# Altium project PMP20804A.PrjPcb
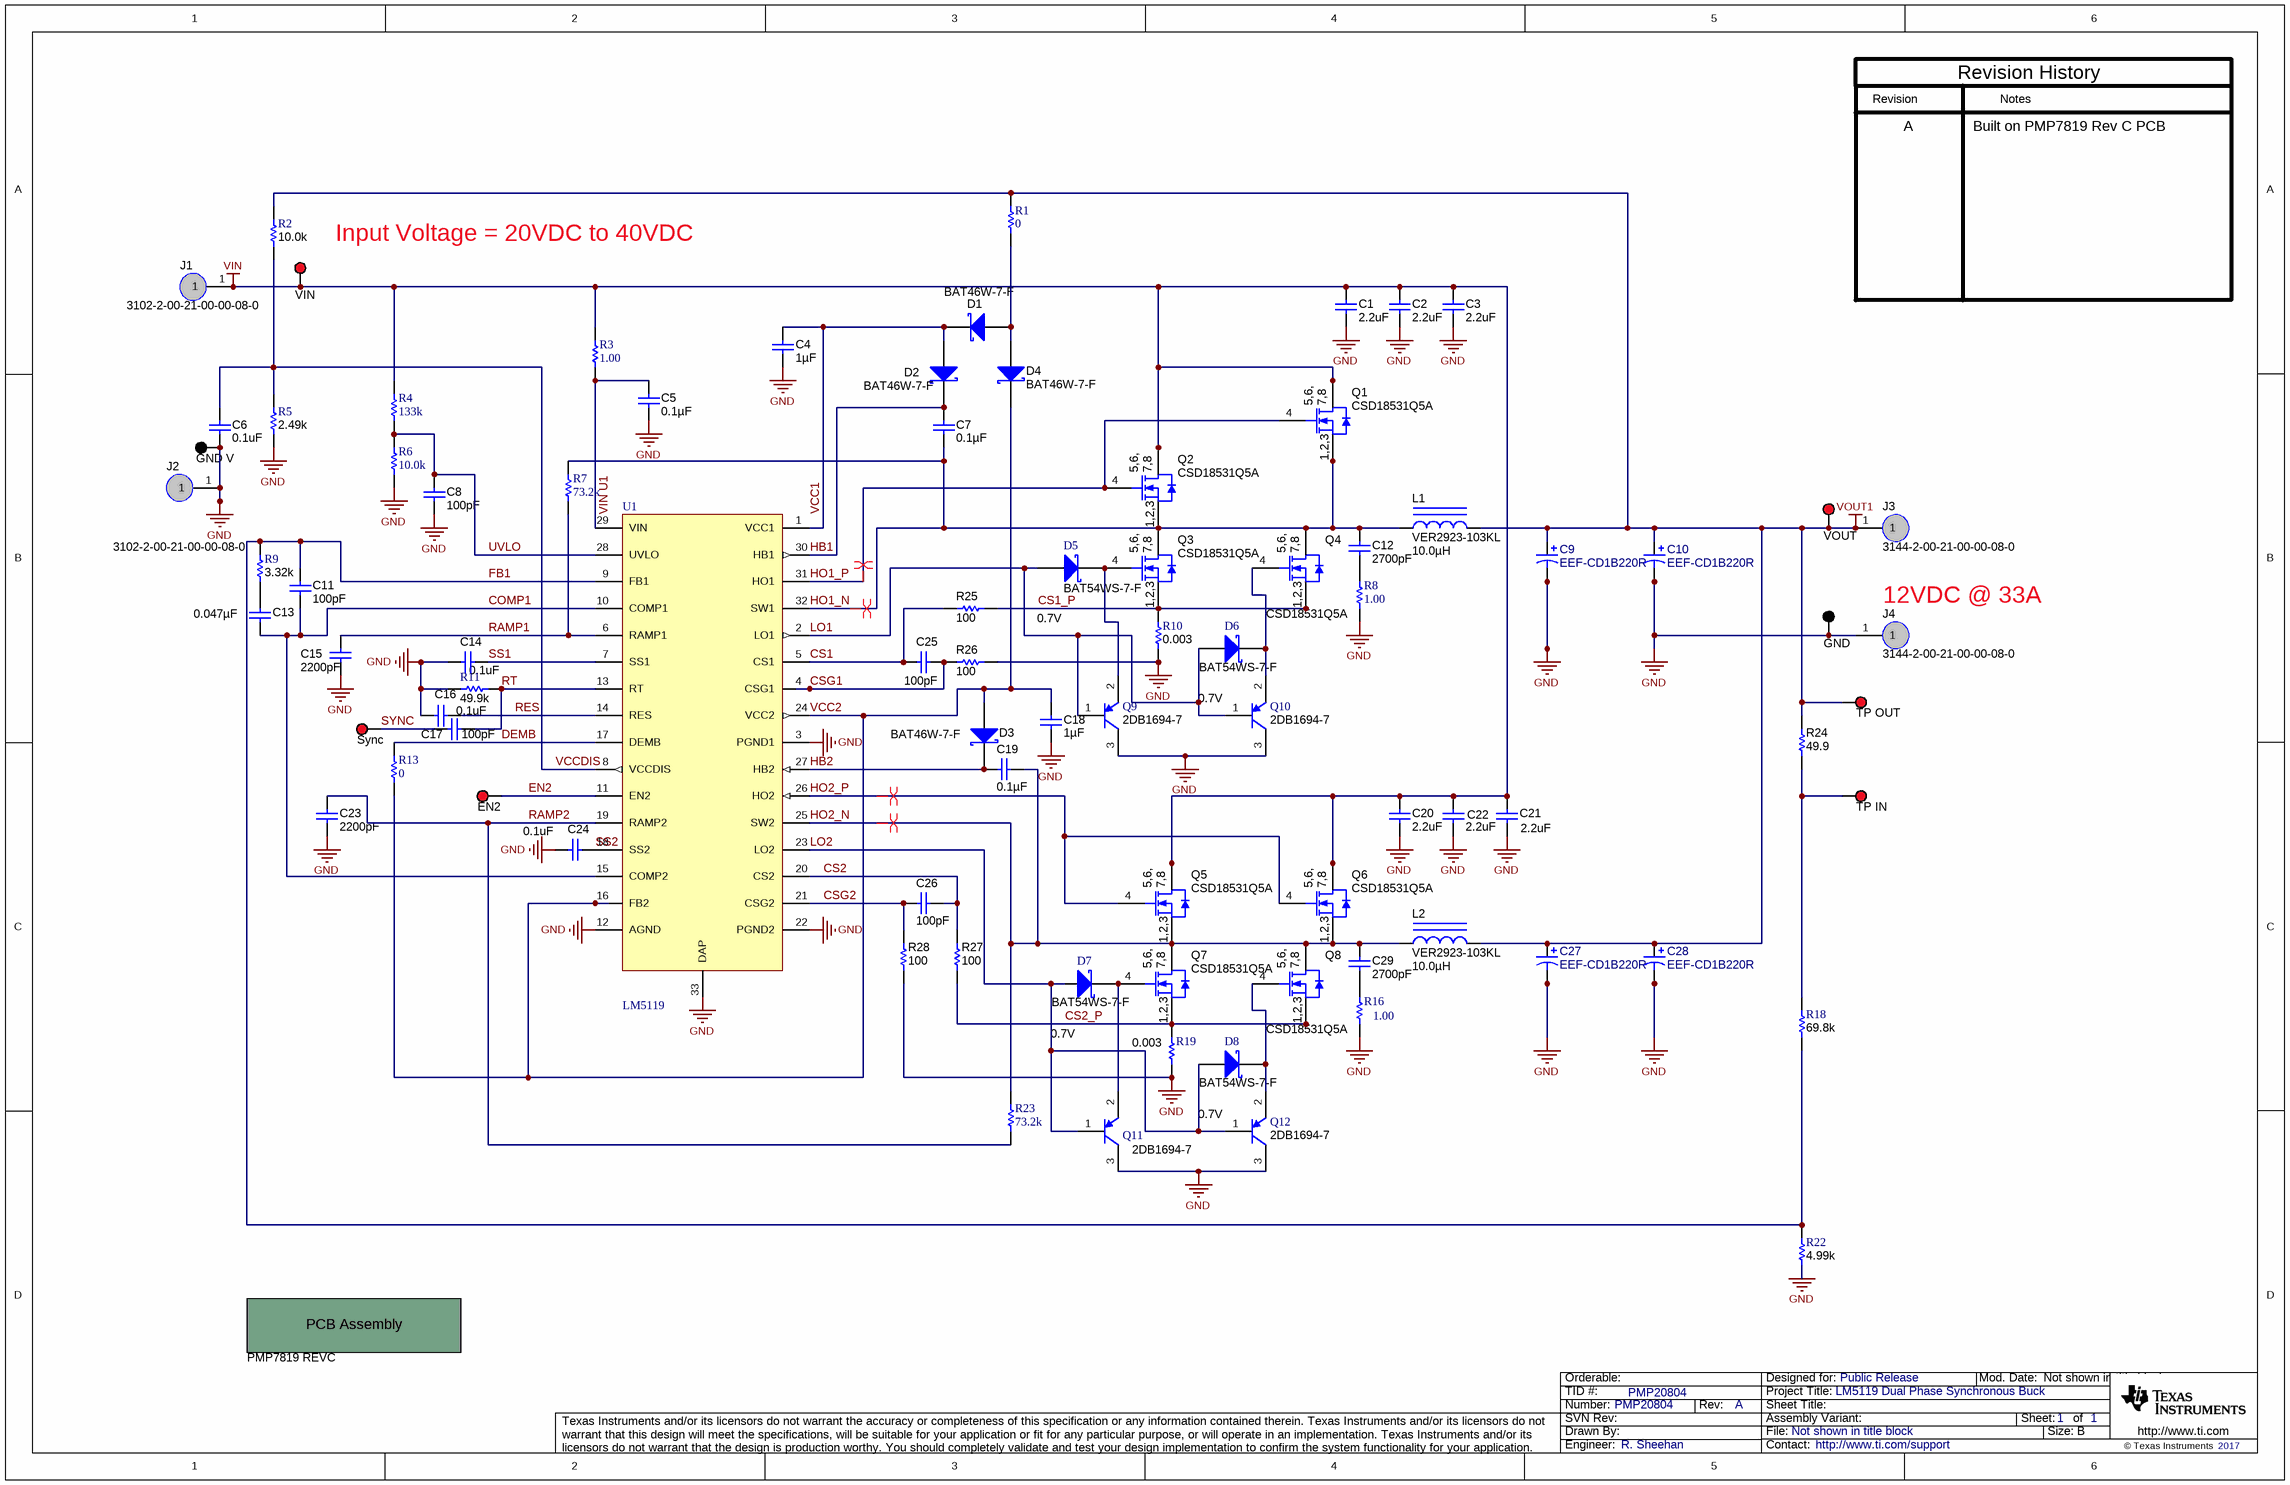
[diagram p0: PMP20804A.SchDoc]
CopyrightYear: 2017; PCB_Rev: C; PRJ_Customer: Public Release; PRJ_Engineer: R. Sheehan; PRJ_Number: PMP20804; PRJ_Title: LM5119 Dual Phase Synchronous Buck; SCH_Rev: A; TechSupport: http://www.ti.com/support; TID: PMP20804
1 sheet, 87 parts. Net scope: global (net labels, ports and power ports of the same name join across sheets).
Board file: PMP7819 REVC.PcbDoc

## Sheet PMP20804A.SchDoc
size 431 x 279 mm; Date: Not shown in title block; ApprovedBy: Not shown in title block; CheckedBy: Not shown in title block; Author: Not shown in title block; CompanyName: Not shown in title block; Engineer: Not shown in title block; Organization: Not shown in title block; Address1: Not shown in title block; Address2: Not shown in title block; Address3: Not shown in title block; Address4: Not shown in title block; DocumentNumber: 1; Revision: Use project parameter SCH_Rev; SheetNumber: 1; SheetTotal: 1; PageSetup: Record=PageOptions¦CenterHorizontal=True¦CenterVertical=True¦PrintScale=1.00¦XCorrection=1.00¦YCorrection=1.00¦PrintKind=0¦BorderSize=5000000¦LeftOffset=0¦BottomOffset=0¦Orientation=2¦PaperLength=1000¦PaperWidth=1000¦Scale=100¦PaperSource=15¦PrintQuality=600¦MediaType=1¦DitherType=10¦PaperKind=Letter¦PrintScaleMode=1

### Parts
!PCBA  PMP7819 REVC  (mechanical)
C1  value 2.2uF  [1210]  (hidden comment: HMK325B7225KN-T)
C2  value 2.2uF  [1210]  (hidden comment: HMK325B7225KN-T)
C3  value 2.2uF  [1210]  (hidden comment: HMK325B7225KN-T)
C4  ValueDisplayed: 1µF  [0603]  (hidden comment: GRM188R71C105KA12D)
C5  ValueDisplayed: 0.1µF  [0805_HV]  (hidden comment: C2012X7R2A104K)
C6  value 0.1uF  [0603]  (hidden comment: C1608X7R1H104K)
C7  ValueDisplayed: 0.1µF  [0603]  (hidden comment: GRM188R72A104KA35D)
C8  value 100pF  [0603]  (hidden comment: 06035A101JAT2A)
C9  EEF-CD1B220R  [CD SP-CAP]
C10  EEF-CD1B220R  [CD SP-CAP]
C11  value 100pF  [0603]  (hidden comment: 06035A101JAT2A)
C12  ValueDisplayed: 2700pF  [0603]  (hidden comment: 06031C272JAT2A)
C13  ValueDisplayed: 0.047µF  [0603]  (hidden comment: C1608X7R1H473K)
C14  value 0.1uF  [0603]  (hidden comment: C1608X7R1H104K)
C15  ValueDisplayed: 2200pF  [0603]  (hidden comment: C0603C222K5RACTU)
C16  value 0.1uF  [0603]  (hidden comment: C1608X7R1H104K)
C17  value 100pF  [0603]  (hidden comment: 06035A101JAT2A)
C18  ValueDisplayed: 1µF  [0603]  (hidden comment: GRM188R71C105KA12D)
C19  ValueDisplayed: 0.1µF  [0603]  (hidden comment: GRM188R72A104KA35D)
C20  value 2.2uF  [1210]  (hidden comment: HMK325B7225KN-T)
C21  value 2.2uF  [1210]  (hidden comment: HMK325B7225KN-T)
C22  value 2.2uF  [1210]  (hidden comment: HMK325B7225KN-T)
C23  ValueDisplayed: 2200pF  [0603]  (hidden comment: C0603C222K5RACTU)
C24  value 0.1uF  [0603]  (hidden comment: C1608X7R1H104K)
C25  ValueDisplayed: 100pF  [0603]  (hidden comment: GRM1885C1H101JA01D)
C26  ValueDisplayed: 100pF  [0603]  (hidden comment: GRM1885C1H101JA01D)
C27  EEF-CD1B220R  [CD SP-CAP]
C28  EEF-CD1B220R  [CD SP-CAP]
C29  ValueDisplayed: 2700pF  [0603]  (hidden comment: 06031C272JAT2A)
D1  BAT46W-7-F  [SOD-123]
D2  BAT46W-7-F  [SOD-123]
D3  BAT46W-7-F  [SOD-123]
D4  BAT46W-7-F  [SOD-123]
D5  BAT54WS-7-F  value 0.7V  [sod-323]
D6  BAT54WS-7-F  value 0.7V  [sod-323]
D7  BAT54WS-7-F  value 0.7V  [sod-323]
D8  BAT54WS-7-F  value 0.7V  [sod-323]
EN2  5000  [Keystone5000]  (value not drawn)
GND  5001  [Keystone5001]  (value not drawn)
GND_V  5001  [Keystone5001]  (value not drawn)
J1  3102-2-00-21-00-00-08-0  [3102-2-00-21-00-00-08-0]
J2  3102-2-00-21-00-00-08-0  [3102-2-00-21-00-00-08-0]
J3  3144-2-00-21-00-00-08-0  [3144-2-00-21-00-00-08-0]
J4  3144-2-00-21-00-00-08-0  [3144-2-00-21-00-00-08-0]
L1  VER2923-103KL  ValueDisplayed: 10.0µH  [VER2923]
L2  VER2923-103KL  ValueDisplayed: 10.0µH  [VER2923]
Q1  CSD18531Q5A  [DQJ0008A]
Q2  CSD18531Q5A  [DQJ0008A]
Q3  CSD18531Q5A  [DQJ0008A]
Q4  CSD18531Q5A  [DQJ0008A]
Q5  CSD18531Q5A  [DQJ0008A]
Q6  CSD18531Q5A  [DQJ0008A]
Q7  CSD18531Q5A  [DQJ0008A]
Q8  CSD18531Q5A  [DQJ0008A]
Q9  2DB1694-7  [SOT-323 DIODES INC]
Q10  2DB1694-7  [SOT-323 DIODES INC]
Q11  2DB1694-7  [SOT-323 DIODES INC]
Q12  2DB1694-7  [SOT-323 DIODES INC]
R1  value 0  [0603]  (hidden comment: CRCW06030000Z0EA)
R2  value 10.0k  [0603]  (hidden comment: CRCW060310K0FKEA)
R3  value 1.00  [0805_HV]  (hidden comment: CRCW08051R00FNEA)
R4  value 133k  [0603]  (hidden comment: CRCW0603133KFKEA)
R5  value 2.49k  [0603]  (hidden comment: CRCW06032K49FKEA)
R6  value 10.0k  [0603]  (hidden comment: CRCW060310K0FKEA)
R7  value 73.2k  [0603]  (hidden comment: CRCW060373K2FKEA)
R8  value 1.00  [1206]  (hidden comment: CRCW12061R00FNEA)
R9  value 3.32k  [0603]  (hidden comment: CRCW06033K32FKEA)
R10  value 0.003  [2010M]  (hidden comment: WSL20103L000FEA)
R11  value 49.9k  [0603]  (hidden comment: CRCW060349K9FKEA)
R13  value 0  [0603]  (hidden comment: CRCW06030000Z0EA)
R16  value 1.00  [1206]  (hidden comment: CRCW12061R00FNEA)
R18  value 69.8k  [0603]  (hidden comment: CRCW060369K8FKEA)
R19  value 0.003  [2010M]  (hidden comment: WSL20103L000FEA)
R22  value 4.99k  [0603]  (hidden comment: CRCW06034K99FKEA)
R23  value 73.2k  [0603]  (hidden comment: CRCW060373K2FKEA)
R24  value 49.9  [0603]  (hidden comment: CRCW060349R9FKEA)
R25  value 100  [0603]  (hidden comment: CRCW0603100RFKEA)
R26  value 100  [0603]  (hidden comment: CRCW0603100RFKEA)
R27  value 100  [0603]  (hidden comment: CRCW0603100RFKEA)
R28  value 100  [0603]  (hidden comment: CRCW0603100RFKEA)
Sync  5000  [Keystone5000]  (value not drawn)
TP_IN  5000  [Keystone5000]  (value not drawn)
TP_OUT  5000  [Keystone5000]  (value not drawn)
U1  LM5119  [SQA32A]
VIN  5000  [Keystone5000]  (value not drawn)
VOUT  5000  [Keystone5000]  (value not drawn)

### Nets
GND: C1.2 C2.2 C3.2 C4.2 C5.2 C6.2 C8.2 C9.2(-) C9.3(-) C10.2(-) C10.3(-) C14.2 C15.2 C16.2 C18.2 C20.2 C21.2 C22.2 C23.2 C24.2 C27.2(-) C27.3(-) C28.2(-) C28.3(-) GND.1 GND_V.1 J2.1 J4.1 Q9.3(C) Q10.3(C) Q11.3(C) Q12.3(C) R5.2 R6.1 R8.2 R10.1 R11.1 R16.2 R19.1 R22.1 R26.2 R28.1 U1.3(PGND1) U1.12(AGND) U1.22(PGND2) U1.33(DAP)
VIN: C1.1 C2.1 C3.1 C20.1 C21.1 C22.1 J1.1 Q1.5(D) Q1.6(D) Q1.7(D) Q1.8(D) Q1.9(D) Q2.5(D) Q2.6(D) Q2.7(D) Q2.8(D) Q2.9(D) Q5.5(D) Q5.6(D) Q5.7(D) Q5.8(D) Q5.9(D) Q6.5(D) Q6.6(D) Q6.7(D) Q6.8(D) Q6.9(D) R3.2 R4.2 VIN.1
VOUT1: C9.1(+) C10.1(+) C27.1(+) C28.1(+) J3.1 L1.2 L2.2 R1.1 R2.2 R24.2 TP_OUT.1 VOUT.1
COMP1: C11.2 C13.2 U1.10(COMP1) U1.15(COMP2)
CS1: C25.2 R25.1 U1.5(CS1)
CS1_P: Q3.1(S) Q3.2(S) Q3.3(S) Q4.1(S) Q4.2(S) Q4.3(S) R10.2 R25.2
CS2: C26.1 R27.2 U1.20(CS2)
CS2_P: Q7.1(S) Q7.2(S) Q7.3(S) Q8.1(S) Q8.2(S) Q8.3(S) R19.2 R27.1
CSG1: C25.1 R26.1 U1.4(CSG1)
CSG2: C26.2 R28.2 U1.21(CSG2)
DEMB: R13.2 U1.17(DEMB)
EN2: EN2.1 U1.11(EN2)
FB1: C11.1 R9.2 R18.1 R22.2 U1.9(FB1)
HB1: C7.2 D2.1(K) U1.30(HB1)
HB2: C19.1 D3.1(K) U1.27(HB2)
HO1_N: C7.1 C12.1 L1.1 Q1.1(S) Q1.2(S) Q1.3(S) Q2.1(S) Q2.2(S) Q2.3(S) Q3.5(D) Q3.6(D) Q3.7(D) Q3.8(D) Q3.9(D) Q4.5(D) Q4.6(D) Q4.7(D) Q4.8(D) Q4.9(D) R7.2 U1.32(SW1)
HO1_P: Q1.4(G) Q2.4(G) U1.31(HO1)
HO2_N: C19.2 C29.1 L2.1 Q5.1(S) Q5.2(S) Q5.3(S) Q6.1(S) Q6.2(S) Q6.3(S) Q7.5(D) Q7.6(D) Q7.7(D) Q7.8(D) Q7.9(D) Q8.5(D) Q8.6(D) Q8.7(D) Q8.8(D) Q8.9(D) R23.2 U1.25(SW2)
HO2_P: Q5.4(G) Q6.4(G) U1.26(HO2)
LO1: D5.2(A) D6.2(A) Q9.1(B) Q10.1(B) U1.2(LO1)
LO2: D7.2(A) D8.2(A) Q11.1(B) Q12.1(B) U1.23(LO2)
RAMP1: C15.1 R7.1 U1.6(RAMP1)
RAMP2: C23.1 R23.1 U1.19(RAMP2)
RES: C16.1 U1.14(RES)
RT: C17.2 R11.2 U1.13(RT)
SS1: C14.1 U1.7(SS1)
SS2: C24.1 U1.18(SS2)
SYNC: C17.1 Sync.1
UVLO: C8.1 R4.1 R6.2 U1.28(UVLO)
VCC1: C4.1 D1.1(K) D2.2(A) U1.1(VCC1)
VCC2: C18.1 D3.2(A) D4.1(K) R13.1 U1.16(FB2) U1.24(VCC2)
VCCDIS: C6.1 R2.1 R5.1 U1.8(VCCDIS)
VIN U1: C5.1 R3.1 U1.29(VIN)
NetC12_2: C12.2 R8.1
NetC13_1: C13.1 R9.1
NetC29_2: C29.2 R16.1
NetD1_2: D1.2(A) D4.2(A) R1.2
NetD5_1: D5.1(K) Q3.4(G) Q9.2(E)
NetD6_1: D6.1(K) Q4.4(G) Q10.2(E)
NetD7_1: D7.1(K) Q7.4(G) Q11.2(E)
NetD8_1: D8.1(K) Q8.4(G) Q12.2(E)
NetR18_2: R18.2 R24.1 TP_IN.1

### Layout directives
differential pair: HO1_N, HO1_P, HO2_N, HO2_P

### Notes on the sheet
- Revision
- Notes
- Revision History
- A
- Built on PMP7819 Rev C PCB
- Input Voltage = 20VDC to 40VDC
- (near J4) 12VDC @ 33A

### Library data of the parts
!PCBA = PCBA: SymbolCreator: a0412235; U/M: EA
C1-C3 C20-C22 = HMK325B7225KN-T: CAP, CERM, 2.2uF, 100V, +/-10%, X7R, 1210; Manufacturer: Taiyo Yuden; Polarized: N; TaMax_C: 125; TaMin_C: -55; Tolerance_%: 10; VDC_V: 100; Cap_F: 0.0000022; CompType: Capacitor; U/M: EA; ValueDisplayed: 2.2µF
C4 C18 = GRM188R71C105KA12D: CAP, CERM, 1uF, 16V, +/-10%, X7R, 0603; Manufacturer: MuRata; ESR_Ohm: 0.011; Polarized: N; TaMax_C: 125; TaMin_C: -55; Tolerance_%: 10; VDC_V: 16; Cap_F: 0.000001; CompType: Capacitor; U/M: EA; Value1: 0.011 ohm
C5 = C2012X7R2A104K: CAP, CERM, 0.1uF, 100V, +/-10%, X7R, 0805; Manufacturer: TDK; Cap_Case: 0805; ESR_Ohm: 0.0158; Polarized: N; TaMax_C: 125; TaMin_C: -55; Tolerance_%: 10; VDC_V: 100; Cap_F: 0.0000001; CompType: Capacitor; Value1: 0.0158 ohm; U/M: EA
C6 C14 C16 C24 = C1608X7R1H104K: CAP, CERM, 0.1uF, 50V, +/-10%, X7R, 0603; Manufacturer: TDK; ESR_Ohm: 0.017; Polarized: N; TaMax_C: 125; TaMin_C: -55; Tolerance_%: 10; VDC_V: 50; Cap_F: 0.0000001; CompType: Capacitor; Value1: 0.017 ohm; U/M: EA; ValueDisplayed: 0.1µF
C7 C19 = GRM188R72A104KA35D: CAP, CERM, 0.1uF, 100V, +/-10%, X7R, 0603; Manufacturer: MuRata; Polarized: N; TaMax_C: 125; TaMin_C: -55; Tolerance_%: 10; VDC_V: 100; Cap_F: 0.0000001; CompType: Capacitor; U/M: EA
C8 C11 C17 = 06035A101JAT2A: CAP, CERM, 100pF, 50V, +/-5%, C0G/NP0, 0603; Manufacturer: AVX; ESR_Ohm: 0.119; Polarized: N; TaMax_C: 125; TaMin_C: -55; Tolerance_%: 5; VDC_V: 50; Cap_F: 0.0000000001; CompType: Capacitor; Value1: 0.119 ohm; U/M: EA
C9 C10 C27 C28 = EEF-CD1B220R: CAP ALUM 22UF 12.5V 20% SMD; Manufacturer: Panasonic-ECG; CompType: Used in BOM report; SymbolVersion: 2012 - 04 - 16; SymbolCreator: cdnlsc
C12 C29 = 06031C272JAT2A: CAP, CERM, 2700pF, 100V, +/-5%, X7R, 0603; Manufacturer: AVX; ESR_Ohm: 0.174; Polarized: N; TaMax_C: 125; TaMin_C: -55; Tolerance_%: 5; VDC_V: 100; Cap_F: 0.0000000027; CompType: Capacitor; Value1: 0.174 ohm; U/M: EA
C13 = C1608X7R1H473K: CAP, CERM, 0.047uF, 50V, +/-10%, X7R, 0603; Manufacturer: TDK; ESR_Ohm: 0.0234; Polarized: N; TaMax_C: 125; TaMin_C: -55; Tolerance_%: 10; VDC_V: 50; Cap_F: 0.000000047; CompType: Capacitor; Value1: 0.0234 ohm; U/M: EA
C15 C23 = C0603C222K5RACTU: CAP, CERM, 2200pF, 50V, +/-10%, X7R, 0603; Manufacturer: Kemet; Polarized: N; TaMax_C: 125; TaMin_C: -55; Tolerance_%: 10; VDC_V: 50; Cap_F: 0.0000000022; CompType: Capacitor; U/M: EA
C25 C26 = GRM1885C1H101JA01D: CAP, CERM, 100pF, 50V, +/-5%, C0G/NP0, 0603; Manufacturer: MuRata; Polarized: N; CompType: Capacitor; U/M: EA; Cap_F: 0.0000000001; Tolerance_%: 5; VDC_V: 50; TaMin_C: -55; TaMax_C: 125
D1-D4 = BAT46W-7-F: Diode, Schottky, 100V, 0.15A, SOD-123; Manufacturer: Diodes Inc.; Vf_V: 0.6; Io_A: 0.15; Vr_V: 100; Value: 0.6V; U/M: EA
D5-D8 = BAT54WS-7-F: Diode, Schottky, 30V, 0.2A, SOD-323; Manufacturer: Diodes Inc.; U/M: EA; Vf_V: 0.7; Io_A: 0.2; Vr_V: 30; TJmax_C: 125
EN2 Sync TP_IN TP_OUT VIN VOUT = 5000: Test Point, TH, Miniature, Red; Manufacturer: Keystone; CompType: Test Point Loop; U/M: EA
GND GND_V = 5001: Test Point, TH, Miniature, Black; Manufacturer: Keystone; CompType: Test Point Loop; U/M: EA
J1 J2 = 3102-2-00-21-00-00-08-0: PC PIN .040 DIA 3102-2 SERIES; Manufacturer: Mill -Max; SymbolVersion: 2011 - 12 - 16; SymbolCreator: cdnlsc; U/M: EA
J3 J4 = 3144-2-00-21-00-00-08-0: CIRCUIT PIN PRNTD .188" .084"; Manufacturer: Mill -Max; SymbolVersion: 2011 - 12 - 16; SymbolCreator: cdnlsc; U/M: EA
L1 L2 = VER2923-103KL: Inductor, Shielded E Core, Ferrite, 10.0uH, 34A, .0023 ohm, SMD; Manufacturer: Coilcraft; Ind_H: 3.3E-6; Imax_A: 30; DCR_ohm: 0.0015; Value1: 0.0023 ohm; Value2: 34.0; U/M: EA
Q1-Q8 = CSD18531Q5A: MOSFET, N-CH, 60 V, 100 A, DQJ0008A (VSONP-8); Manufacturer: Texas Instruments; Alternate Manufacturer: None; Value: 60V; ChType: N; VdsMax_V: 60; Value1: 0.0058 ohm; Rdson45_ohm: 0.0058; Value2: 36 nC; QgTyp_nC: 36; Vgs_V: 20; IdsMax_A: 100; U/M: EA; SizeAreaWB_mm2: 55.2; SizeArea_mm2: 29.4; SizeX_mm: 6; SizeY_mm: 4.9; SizeZ_mm: 1.1; AEC Category: Q101
Q9-Q12 = 2DB1694-7: TRANS BIPO PNP 30V 1A SOT-323; Manufacturer: Diodes Inc.; CompType: BJT; U/M: EA; PNP: 1; NPN: 0; Vceo_V: 30; Vcesat1_V: 0.075; Value: 0.075V; IcRated_A: 0.1; Value1: 0.1A; HfeMax: 600
R1 R13 = CRCW06030000Z0EA: RES, 0 ohm, 5%, 0.1W, 0603; Manufacturer: Vishay-Dale; CompType: Resistor; Tolerance_%: 5; VDC_V: 75; Power_W: 0.1; Value_Code: 0000; EIA_Code: E24; U/M: EA
R2 = CRCW060310K0FKEA: RES, 10.0k ohm, 1%, 0.1W, 0603; Manufacturer: Vishay-Dale; CompType: Resistor; Tolerance_%: 1; VDC_V: 75; Power_W: 0.1; Res_ohm: 10000; Value_Code: 10k0; EIA_Code: E96; U/M: EA; TempCo: 100 ppm/C
R3 = CRCW08051R00FNEA: RES, 1.00 ohm, 1%, 0.125W, 0805; Manufacturer: Vishay-Dale; CompType: Resistor; Tolerance_%: 1; VDC_V: 150; Power_W: 0.125; Value_Code: 1R00; EIA_Code: E96; U/M: EA
R4 = CRCW0603133KFKEA: RES, 133k ohm, 1%, 0.1W, 0603; Manufacturer: Vishay-Dale; CompType: Resistor; Tolerance_%: 1; VDC_V: 75; Power_W: 0.1; Res_Ohm: 133000; EIA_Code: E96; U/M: EA
R5 = CRCW06032K49FKEA: RES, 2.49k ohm, 1%, 0.1W, 0603; Manufacturer: Vishay-Dale; CompType: Resistor; Tolerance_%: 1; VDC_V: 75; Power_W: 0.1; Res_ohm: 2490; Value_Code: 2k49; EIA_Code: E96; U/M: EA; TempCo: 100 ppm/C
R6 = CRCW060310K0FKEA: RES, 10.0k ohm, 1%, 0.1W, 0603; Manufacturer: Vishay-Dale; CompType: Resistor; Tolerance_%: 1; VDC_V: 75; Power_W: 0.1; Res_Ohm: 10000; Value_Code: 10k0; EIA_Code: E96; U/M: EA
R7 R23 = CRCW060373K2FKEA: RES, 73.2k ohm, 1%, 0.1W, 0603; Manufacturer: Vishay-Dale; CompType: Resistor; Tolerance_%: 1; VDC_V: 75; Power_W: 0.1; Res_Ohm: 73200; Value_Code: 73k2; EIA_Code: E96; U/M: EA
R8 R16 = CRCW12061R00FNEA: RES, 1.00 ohm, 1%, 0.25W, 1206; Manufacturer: Vishay-Dale; CompType: Resistor; Tolerance_%: 1; VDC_V: 200; Power_W: 0.25; Value_Code: 1R00; EIA_Code: E96; U/M: EA
R9 = CRCW06033K32FKEA: RES, 3.32k ohm, 1%, 0.1W, 0603; Manufacturer: Vishay-Dale; CompType: Resistor; Tolerance_%: 1; VDC_V: 75; Power_W: 0.1; Res_ohm: 3320; Value_Code: 3k32; EIA_Code: E96; U/M: EA; TempCo: 100 ppm/C
R10 R19 = WSL20103L000FEA: RES, 0.003 ohm, 1%, 0.5W, 2010; Manufacturer: Vishay-Dale; CompType: Resistor; Tolerance_%: 1; Power_W: 0.5; Value_Code: R003; EIA_Code: E96; U/M: EA; TempCo: 150 ppm/C
R11 = CRCW060349K9FKEA: RES, 49.9k ohm, 1%, 0.1W, 0603; Manufacturer: Vishay-Dale; CompType: Resistor; Tolerance_%: 1; VDC_V: 75; Power_W: 0.1; Res_ohm: 49900; Value_Code: 49k9; EIA_Code: E96; U/M: EA; TempCo: 100 ppm/C
R18 = CRCW060369K8FKEA: RES, 69.8k ohm, 1%, 0.1W, 0603; Manufacturer: Vishay-Dale; CompType: Resistor; Tolerance_%: 1; VDC_V: 75; Power_W: 0.1; Res_ohm: 69800; Value_Code: 69k8; EIA_Code: E96; U/M: EA; TempCo: 100 ppm/C
R22 = CRCW06034K99FKEA: RES, 4.99k ohm, 1%, 0.1W, 0603; Manufacturer: Vishay-Dale; CompType: Resistor; Tolerance_%: 1; VDC_V: 75; Power_W: 0.1; Res_ohm: 4990; Value_Code: 4k99; EIA_Code: E96; U/M: EA; TempCo: 100 ppm/C
R24 = CRCW060349R9FKEA: RES, 49.9 ohm, 1%, 0.1W, 0603; Manufacturer: Vishay-Dale; CompType: Resistor; Value_Code: 49R9; Tolerance_%: 1; Power_W: 0.1; VDC_V: 75; TempCo: 100 ppm/C; EIA_Code: E96; U/M: EA
R25-R28 = CRCW0603100RFKEA: RES, 100 ohm, 1%, 0.1W, 0603; Manufacturer: Vishay-Dale; CompType: Resistor; Value_Code: 100R; Tolerance_%: 1; Power_W: 0.1; VDC_V: 75; TempCo: 100 ppm/C; EIA_Code: E96; U/M: EA
U1 = LM5119PSQE/NOPB: IC CTRL SYNC BUCK DUAL 32-LLP; Manufacturer: National Semiconductor; CompType: Switcher; PowerWise: Y

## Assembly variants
001: not fitted EN2 Sync TP IN TP OUT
